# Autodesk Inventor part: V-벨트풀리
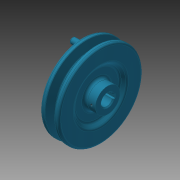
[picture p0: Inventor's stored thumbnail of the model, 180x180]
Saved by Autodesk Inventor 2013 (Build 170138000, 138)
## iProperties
Company: 한국ATC센터
Created: 2015-12
Part Number: V-벨트풀리
Document SubType Name: Modeling
Designer: mdu
Density: 7.25 g/cm^3
Mass: 596.61 g
Surface Area: 212.231 cm^2
Volume: 82.291 cm^3
Material: 주철
Author: mdu
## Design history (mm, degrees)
sketch "스케치1"
  geometry: L1 (-13, 0)-(13, 0); L2 (-13, 0)-(-13, 12.5); L3 (-13, 12.5)-(-9, 12.5); L4 (-9, 12.5)-(-9, 23); L5 (-9, 23)-(-13, 27); L6 (-13, 27)-(-13, 42.7); L7 (-13, 42.7)-(-8.325, 42.7); L8 (-8.325, 42.7)-(-5.574, 33.7); L9 (-5.574, 33.7)-(-1.426, 33.7); L10 (-1.426, 33.7)-(1.325, 42.7); L11 (1.325, 42.7)-(6, 42.7); L12 (6, 42.7)-(6, 27); L13 (6, 27)-(2, 23); L14 (2, 23)-(2, 12.5); L15 (2, 12.5)-(13, 12.5); L16 (13, 12.5)-(13, 0); L17 (-7.5, 40)-(0.5, 40); 2 further points
  constraints: 34 end point, 6 parallel, 5 collinear, 5 equal length, 4 perpendicular, 2 point on line, 1 coincident, 1 horizontal, 1 midpoint
  dimensions: "d0" = 26 distance of L1.start L1.end; "d1" = 2.7 distance between parallel lines of L7 L17; "d2" = 6.3 distance between parallel lines of L9 L17; "d3" = 8 distance of L17.start L17.end; "d4" = 34 deg angle of L10 L8; "d5" = 19 distance between parallel lines of L12 L6; "d7" = 25 diameter of L15 L1; "d8" = 46 diameter of L13.end L1; "d9" = 54 diameter of L12.end L1; "d10" = 4 distance between parallel lines of L2 L4; "d11" = 80 diameter of L17 L1
revolve "회전1" sketch "스케치1" stored, may be unused: angle "d12" = 90 deg
sketch "스케치2"
  geometry: L1 (-2, 5.657)-(-2, 7.8); L2 (-2, 7.8)-(2, 7.8); L3 (2, 7.8)-(2, 5.657); A1 r 6 centre (0, 0) between (-2, 5.657) and (2, 5.657); 1 further point
  constraints: 6 end point, 2 parallel, 2 point on circle, 1 centre point, 1 coincident, 1 perpendicular, 1 vertical
  dimensions: "d13" = 12 diameter of A1; "d14" = 13.8 dimension on A1 L2; "d15" = 4 distance of L1.end L2.end
extrude "돌출1" cut sketch "스케치2" stored distance "d16" = 10; taper "d17" = 0 deg
node "작업 평면1"
sketch "스케치3"
  geometry: L1 (-5.5, 12.5)-(-5.5, -12.5) reference; L2 (20.5, 27)-(20.5, -27) reference; 3 further points
  constraints: 1 horizontal alignment, 1 midpoint
  dimensions: "d18" = 4 distance from line of point (-1.5, 0) L1; "d33" = 22 distance from line of point (-1.5, 0) L2 (derived)
hole "구멍1" sketch "스케치3" at (-1.5, 0) diameter "d19" = 2.459; stored, may be unused: countersink angle "d23" = 90 deg, drill point angle "d25" = 118 deg; dims "d20" = 6, "d21" = 4, "d22" = 2, "d24" = 8
fillet "모깎기1" dims "d26" = 2, "d27" = 0.5, "d28" = 1, "d29" = 3
chamfer "모따기1" distance "d30" = 1; stored, may be unused: second distance "d31" = 2, angle "d32" = 45 deg
sketch "스케치4" dims "d35" = 70
  geometry: C1 r 3 at (35, 0); 2 further points
  constraints: 2 horizontal alignment, 1 centre point, 1 coincident, 2 other
  dimensions: "d34" = 6 diameter of C1
extrude "돌출2" join sketch "스케치4" distance "d36" = 10; taper "d37" = 0 deg
fillet "모깎기2" dims "d38" = 0.5, "d39" = 1
node "솔리드1"
